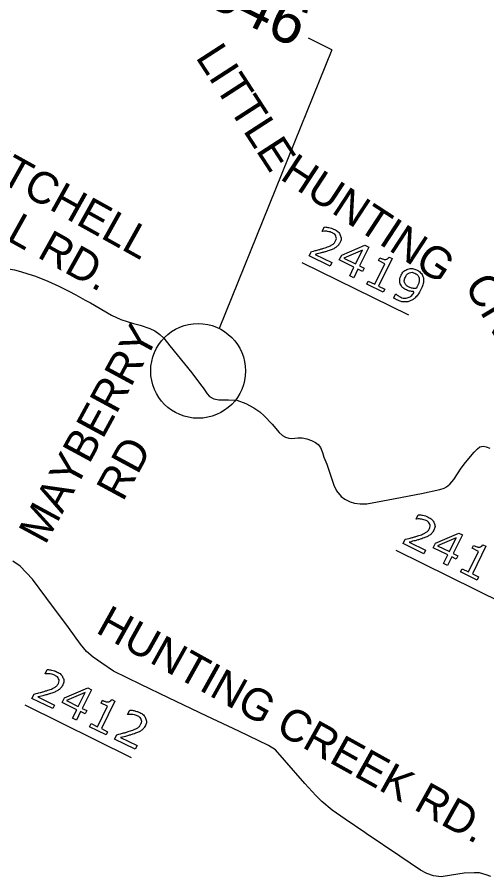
# Model space of a CAD drawing. Extents: x 1428128 to 1430390, y 857947 to 859822.
# Drawn here: x 1429086 to 1429189.4, y 859245.9 to 859435.3 of the extents above; entities that cross this region are included whole.
import ezdxf

# ---------------------------------------------------------------- set-up
doc = ezdxf.new("R2010")
doc.units = 0
doc.layers.add('Old_Level_1', color=7, linetype='Continuous')
doc.layers.add('Sheet Title CELL', color=7, linetype='Continuous')

msp = doc.modelspace()

# ---------------------------------------------------------------- linework, layer by layer
at = {"layer": 'Old_Level_1'}
for p, q in [((1429155.3, 859428.14), (1429150.15, 859430.68)), ((1429155.3, 859428.14), (1429130.47, 859366.76)), ((1429148.72, 859381.29), (1429172.18, 859369.75)), ((1429169.37, 859317.89), (1429192.89, 859306.32)), ((1429087.67, 859283.79), (1429111.15, 859272.24))]:
    msp.add_line(p, q, dxfattribs=at)
for points in [[(1429153.25, 859388.13), (1429153.2, 859388.15), (1429153.67, 859389.1)], [(1429154.89, 859380.49), (1429150.33, 859382.73), (1429150.8, 859383.68)], [(1429162.04, 859379.32), (1429161.04, 859379.81), (1429160.1, 859377.92), (1429159.24, 859378.35), (1429160.17, 859380.24), (1429156.94, 859381.83), (1429157.46, 859382.87), (1429162.58, 859385.06), (1429163.42, 859384.65), (1429161.39, 859380.54), (1429162.39, 859380.05), (1429162.04, 859379.32)], [(1429160.53, 859380.97), (1429162.02, 859384.01), (1429157.91, 859382.25), (1429160.53, 859380.97)], [(1429151.65, 859383.05), (1429155.27, 859381.27), (1429154.89, 859380.49)], [(1429166.63, 859374.71), (1429162.99, 859376.5), (1429163.32, 859377.19), (1429164.73, 859376.5), (1429166.94, 859381.01), (1429165.54, 859381.7), (1429165.85, 859382.31)], [(1429167.88, 859382.48), (1429168.58, 859382.14), (1429165.59, 859376.07), (1429166.97, 859375.4), (1429166.63, 859374.71)], [(1429168.94, 859373.54), (1429169.37, 859374.4), (1429169.41, 859374.38)], [(1429173.89, 859324.73), (1429173.85, 859324.75), (1429174.32, 859325.7)], [(1429182.69, 859315.92), (1429181.69, 859316.42), (1429180.75, 859314.52), (1429179.88, 859314.95), (1429180.82, 859316.84), (1429177.59, 859318.43), (1429178.1, 859319.47), (1429183.23, 859321.66), (1429184.06, 859321.25), (1429182.04, 859317.14), (1429183.04, 859316.65), (1429182.69, 859315.92)], [(1429175.54, 859317.09), (1429170.98, 859319.33), (1429171.44, 859320.28)], [(1429172.3, 859319.65), (1429175.92, 859317.87), (1429175.54, 859317.09)], [(1429181.17, 859317.57), (1429182.67, 859320.61), (1429178.56, 859318.85), (1429181.17, 859317.57)], [(1429187.28, 859311.31), (1429183.63, 859313.1), (1429183.97, 859313.79), (1429185.37, 859313.1), (1429187.59, 859317.61), (1429186.19, 859318.3), (1429186.49, 859318.91)], [(1429188.53, 859319.08), (1429189.23, 859318.74), (1429186.24, 859312.67), (1429187.61, 859312), (1429187.28, 859311.31)], [(1429092.2, 859290.63), (1429092.15, 859290.65), (1429092.62, 859291.6)], [(1429100.99, 859281.82), (1429099.99, 859282.32), (1429099.06, 859280.42), (1429098.19, 859280.85), (1429099.12, 859282.74), (1429095.9, 859284.33), (1429096.41, 859285.37), (1429101.54, 859287.56), (1429102.37, 859287.15), (1429100.35, 859283.04), (1429101.35, 859282.55), (1429100.99, 859281.82)], [(1429093.84, 859282.99), (1429089.28, 859285.23), (1429089.75, 859286.18)], [(1429090.6, 859285.55), (1429094.22, 859283.77), (1429093.84, 859282.99)], [(1429099.48, 859283.47), (1429100.97, 859286.51), (1429096.87, 859284.75), (1429099.48, 859283.47)], [(1429105.58, 859277.21), (1429101.94, 859279), (1429102.28, 859279.69), (1429103.68, 859279), (1429105.9, 859283.51), (1429104.5, 859284.2), (1429104.8, 859284.81)], [(1429106.83, 859284.98), (1429107.53, 859284.64), (1429104.55, 859278.57), (1429105.92, 859277.9), (1429105.58, 859277.21)], [(1429110.39, 859281.68), (1429110.34, 859281.7), (1429110.81, 859282.65)], [(1429112.03, 859274.04), (1429107.47, 859276.28), (1429107.94, 859277.23)], [(1429108.79, 859276.6), (1429112.41, 859274.82), (1429112.03, 859274.04)]]:
    msp.add_lwpolyline(points, dxfattribs=at)
for points in [[(1429153.67, 859389.1), (1429154.07, 859389.1), (1429154.67, 859388.97), (1429155.27, 859388.83), (1429155.77, 859388.59), (1429156.81, 859388.08), (1429157.15, 859387.29), (1429157.49, 859386.5), (1429157.07, 859385.65), (1429156.88, 859385.26), (1429156.62, 859384.98), (1429156.36, 859384.7), (1429156.03, 859384.49), (1429155.71, 859384.3), (1429155.34, 859384.14), (1429154.97, 859383.99), (1429154.47, 859383.83), (1429153.75, 859383.59), (1429153.02, 859383.4), (1429152.28, 859383.21), (1429151.65, 859383.05)], [(1429150.8, 859383.68), (1429151.47, 859383.85), (1429152.15, 859384.03), (1429152.83, 859384.2), (1429153.44, 859384.4), (1429154.72, 859384.81), (1429155.29, 859385.14), (1429155.85, 859385.48), (1429156.13, 859386.05), (1429156.39, 859386.58), (1429156.19, 859387.04), (1429155.99, 859387.51), (1429155.37, 859387.82), (1429154.95, 859388.02), (1429154.4, 859388.11), (1429153.85, 859388.2), (1429153.25, 859388.13)], [(1429165.85, 859382.31), (1429166.13, 859382.17), (1429166.48, 859382.06), (1429166.83, 859381.95), (1429167.04, 859381.96), (1429167.3, 859381.97), (1429167.51, 859382.08), (1429167.71, 859382.2), (1429167.88, 859382.48)], [(1429169.41, 859374.38), (1429169.51, 859374.25), (1429169.72, 859374.07), (1429169.93, 859373.89), (1429170.22, 859373.75), (1429171.22, 859373.25), (1429172.08, 859373.57), (1429172.94, 859373.89), (1429173.55, 859374.9), (1429173.01, 859374.86), (1429172.58, 859374.93), (1429172.16, 859375), (1429171.72, 859375.22), (1429171.31, 859375.42), (1429171.01, 859375.67), (1429170.71, 859375.92), (1429170.49, 859376.32), (1429170.23, 859376.79), (1429170.24, 859377.31), (1429170.25, 859377.84), (1429170.54, 859378.43), (1429171.05, 859379.46), (1429172.04, 859379.78), (1429173.04, 859380.09), (1429174.02, 859379.61), (1429174.5, 859379.37), (1429174.84, 859379.01), (1429175.19, 859378.66), (1429175.35, 859378.2), (1429175.55, 859377.64), (1429175.47, 859376.94), (1429175.38, 859376.25), (1429174.92, 859375.31)], [(1429174.1, 859375.96), (1429174.45, 859376.66), (1429174.51, 859377.16), (1429174.58, 859377.66), (1429174.44, 859378.02), (1429174.33, 859378.32), (1429174.13, 859378.53), (1429173.93, 859378.74), (1429173.64, 859378.88), (1429172.99, 859379.2), (1429172.42, 859378.98), (1429171.84, 859378.76), (1429171.48, 859378.02), (1429171.26, 859377.59), (1429171.25, 859377.26), (1429171.24, 859376.93), (1429171.43, 859376.58), (1429171.56, 859376.34), (1429171.78, 859376.17), (1429172, 859376.01), (1429172.3, 859375.86), (1429172.65, 859375.69), (1429173.06, 859375.6), (1429173.47, 859375.52), (1429173.87, 859375.55), (1429173.93, 859375.64), (1429173.98, 859375.73), (1429174.03, 859375.82), (1429174.1, 859375.96)], [(1429174.92, 859375.31), (1429174.49, 859374.43), (1429173.93, 859373.81), (1429173.38, 859373.19), (1429172.72, 859372.88), (1429172.06, 859372.57), (1429171.3, 859372.6), (1429170.54, 859372.62), (1429169.71, 859373.03), (1429169.47, 859373.15), (1429169.27, 859373.27), (1429169.08, 859373.4), (1429168.94, 859373.54)], [(1429171.44, 859320.28), (1429172.12, 859320.46), (1429172.8, 859320.63), (1429173.48, 859320.8), (1429174.09, 859321), (1429175.37, 859321.41), (1429175.93, 859321.75), (1429176.5, 859322.08), (1429176.78, 859322.66), (1429177.04, 859323.18), (1429176.84, 859323.65), (1429176.64, 859324.11), (1429176.02, 859324.42), (1429175.6, 859324.62), (1429175.05, 859324.71), (1429174.5, 859324.81), (1429173.89, 859324.73)], [(1429174.32, 859325.7), (1429174.72, 859325.7), (1429175.32, 859325.57), (1429175.92, 859325.44), (1429176.42, 859325.19), (1429177.46, 859324.68), (1429177.8, 859323.89), (1429178.14, 859323.1), (1429177.72, 859322.25), (1429177.53, 859321.87), (1429177.27, 859321.58), (1429177.01, 859321.3), (1429176.67, 859321.09), (1429176.36, 859320.9), (1429175.99, 859320.75), (1429175.62, 859320.59), (1429175.12, 859320.43), (1429174.4, 859320.19), (1429173.67, 859320), (1429172.93, 859319.81), (1429172.3, 859319.65)], [(1429186.49, 859318.91), (1429186.78, 859318.77), (1429187.13, 859318.66), (1429187.48, 859318.55), (1429187.69, 859318.56), (1429187.95, 859318.57), (1429188.16, 859318.68), (1429188.36, 859318.8), (1429188.53, 859319.08)], [(1429089.75, 859286.18), (1429090.42, 859286.36), (1429091.1, 859286.53), (1429091.78, 859286.7), (1429092.39, 859286.9), (1429093.67, 859287.31), (1429094.24, 859287.65), (1429094.8, 859287.98), (1429095.09, 859288.56), (1429095.34, 859289.08), (1429095.14, 859289.55), (1429094.94, 859290.01), (1429094.32, 859290.32), (1429093.91, 859290.52), (1429093.36, 859290.61), (1429092.8, 859290.71), (1429092.2, 859290.63)], [(1429092.62, 859291.6), (1429093.02, 859291.6), (1429093.62, 859291.47), (1429094.22, 859291.34), (1429094.72, 859291.09), (1429095.76, 859290.58), (1429096.1, 859289.79), (1429096.44, 859289), (1429096.02, 859288.15), (1429095.84, 859287.76), (1429095.58, 859287.48), (1429095.31, 859287.2), (1429094.98, 859286.99), (1429094.66, 859286.8), (1429094.29, 859286.64), (1429093.92, 859286.49), (1429093.42, 859286.33), (1429092.7, 859286.09), (1429091.97, 859285.9), (1429091.23, 859285.71), (1429090.6, 859285.55)], [(1429104.8, 859284.81), (1429105.08, 859284.67), (1429105.43, 859284.56), (1429105.78, 859284.45), (1429105.99, 859284.46), (1429106.26, 859284.47), (1429106.46, 859284.58), (1429106.67, 859284.7), (1429106.83, 859284.98)], [(1429107.94, 859277.23), (1429108.61, 859277.41), (1429109.29, 859277.58), (1429109.97, 859277.75), (1429110.58, 859277.95), (1429111.86, 859278.36), (1429112.43, 859278.7), (1429112.99, 859279.03), (1429113.27, 859279.61), (1429113.53, 859280.13), (1429113.33, 859280.6), (1429113.13, 859281.06), (1429112.51, 859281.37), (1429112.1, 859281.57), (1429111.54, 859281.66), (1429110.99, 859281.76), (1429110.39, 859281.68)], [(1429110.81, 859282.65), (1429111.21, 859282.65), (1429111.81, 859282.52), (1429112.41, 859282.39), (1429112.91, 859282.14), (1429113.95, 859281.63), (1429114.29, 859280.84), (1429114.63, 859280.05), (1429114.21, 859279.2), (1429114.02, 859278.81), (1429113.76, 859278.53), (1429113.5, 859278.25), (1429113.17, 859278.04), (1429112.85, 859277.85), (1429112.48, 859277.69), (1429112.11, 859277.54), (1429111.61, 859277.38), (1429110.89, 859277.14), (1429110.16, 859276.95), (1429109.42, 859276.76), (1429108.79, 859276.6)]]:
    msp.add_open_spline(points, degree=3, dxfattribs=at)
at = {"layer": 'Sheet Title CELL'}
for points in [[(1429055.75, 859393.46), (1429062.4, 859389.46), (1429065.08, 859388.06), (1429069.93, 859386.03), (1429071.79, 859385.08), (1429077.86, 859381.29), (1429079.94, 859380.33), (1429080.76, 859380.2), (1429082.31, 859380.07), (1429083.7, 859379.92), (1429085.4, 859379.65), (1429086.76, 859379.31), (1429088.37, 859378.78), (1429090.08, 859378.24), (1429092.8, 859377.13), (1429095.18, 859376.06), (1429097.39, 859374.95), (1429098.96, 859374.14), (1429101.01, 859372.97), (1429102.13, 859372.36), (1429106.77, 859369.68), (1429108.85, 859368.7), (1429111.63, 859367.82)], [(1429111.63, 859367.82), (1429113.08, 859367.45), (1429115.22, 859366.71), (1429116.34, 859366.19), (1429117.4, 859365.42), (1429117.41, 859365.41)], [(1429117.41, 859365.41), (1429118.3, 859364.6), (1429119.63, 859362.88)], [(1429119.63, 859362.88), (1429121.21, 859360.93), (1429124.5, 859357), (1429126.35, 859354.42)], [(1429126.35, 859354.42), (1429127, 859353.64), (1429127.86, 859352.33), (1429128.36, 859351.77), (1429129.3, 859351.2), (1429130.38, 859350.98), (1429132.17, 859351), (1429132.51, 859350.99)], [(1429132.51, 859350.99), (1429134.39, 859350.94), (1429136.39, 859350.24), (1429138.15, 859349.25), (1429139.44, 859348.37), (1429140.42, 859347.48), (1429142.16, 859345.62), (1429143.73, 859343.85), (1429144.45, 859343.15), (1429145.09, 859342.8), (1429145.86, 859342.58), (1429146.46, 859342.53), (1429147.83, 859342.64), (1429148.78, 859342.67), (1429149.81, 859342.42), (1429150.83, 859342.07), (1429151.67, 859341.63), (1429152.27, 859341.18), (1429152.8, 859340.48), (1429153.26, 859339.38), (1429153.5, 859338.39), (1429154.19, 859336.86), (1429155.7, 859332.18), (1429156.32, 859330.97), (1429157.38, 859329.69), (1429158.16, 859329.12), (1429159.32, 859328.55), (1429160.25, 859328.28), (1429161.53, 859328.09), (1429163.02, 859328.07), (1429167.72, 859329), (1429175.06, 859330.39), (1429179.07, 859331.24), (1429180.02, 859331.52), (1429180.57, 859331.87), (1429181.3, 859332.46), (1429182.14, 859333.43), (1429183.78, 859335.94), (1429184.75, 859337.21), (1429186.6, 859339.49), (1429187.36, 859340.22), (1429187.91, 859340.63), (1429188.61, 859340.79), (1429189.3, 859340.67), (1429190.08, 859340.35)], [(1429162.59, 859255.67), (1429158.25, 859258.62), (1429155.33, 859260.62), (1429153.1, 859262.48), (1429151.74, 859263.82), (1429149.37, 859266.49), (1429144.87, 859271.64), (1429142.86, 859273.88), (1429141.37, 859274.82), (1429134.81, 859277.99), (1429127.78, 859281.32), (1429119.35, 859285.34), (1429113.23, 859288.26), (1429107.22, 859291.23), (1429104.63, 859292.96), (1429102.76, 859294.32), (1429101.31, 859295.57), (1429099.95, 859297.16), (1429097.32, 859300.82), (1429092.53, 859307.23), (1429089.41, 859311.53), (1429086.65, 859314.38), (1429085.03, 859315.44)], [(1429190.27, 859245.98), (1429189.29, 859246.36), (1429187.78, 859246.78), (1429186.63, 859246.83), (1429184.43, 859246.7), (1429181.61, 859246.27), (1429179.35, 859245.92), (1429177.68, 859246.13), (1429176.19, 859246.68), (1429174.79, 859247.42), (1429170.27, 859250.44), (1429162.86, 859255.49), (1429162.59, 859255.67)]]:
    msp.add_lwpolyline(points, dxfattribs=at)
msp.add_circle((1429125.86, 859357.39), 10.44, dxfattribs=at)

# ---------------------------------------------------------------- texts
at = {"layer": 'Old_Level_1'}
for s, height, rotation, p in [('B-4846', 10, 333.8001, (1429108.37, 859447.54)), ('LITTLE', 7, 302.919, (1429125.16, 859426.5)), ('MITCHELL', 7, 330.9009, (1429072.81, 859404.25)), ('HUNTING', 7, 326.812, (1429143.64, 859399.76)), ('MILL RD.', 7, 330.9009, (1429069.73, 859393.94)), ('CREEK RD.', 7, 300.914, (1429184.33, 859376.23)), ('MAYBERRY', 7, 61.531, (1429092.19, 859318.87)), ('RD', 7, 61.531, (1429109.3, 859328.4)), ('HUNTING CREEK RD.', 7, 330.9009, (1429103.07, 859299.86))]:
    msp.add_text(s, height=height, rotation=rotation, dxfattribs=at).set_placement(p)

doc.saveas('drawing.dxf')
